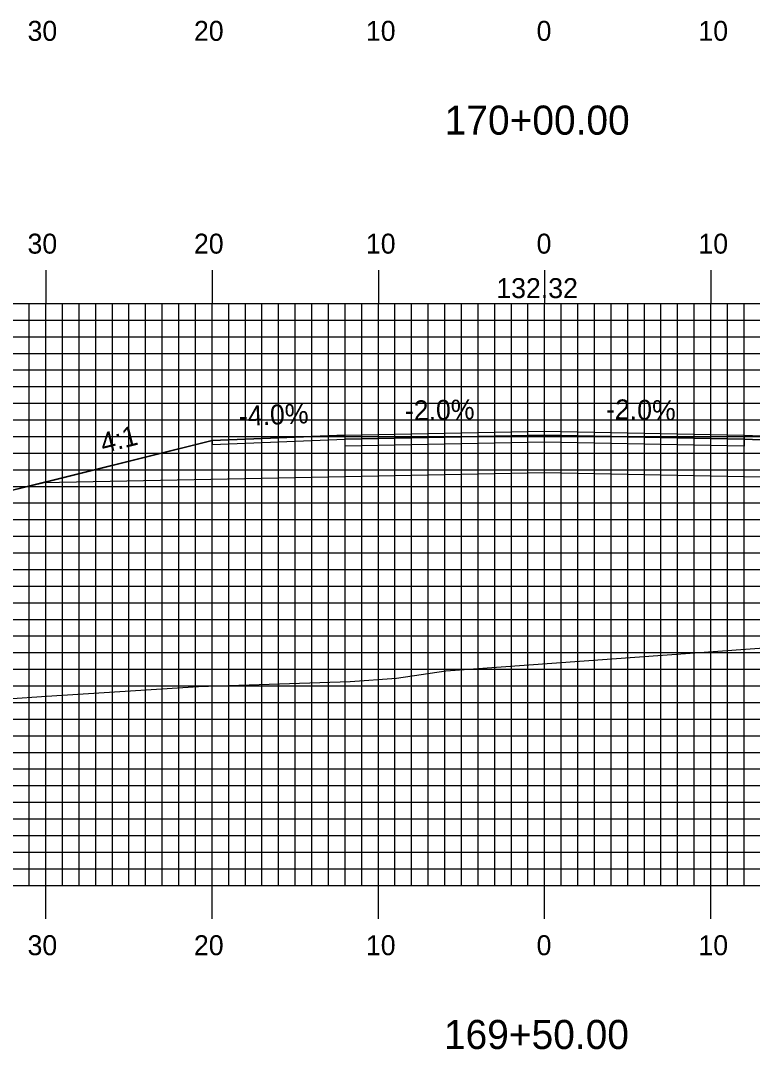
# Model space of a CAD drawing. Extents: x 1782254 to 1782597, y 442591 to 442811.
# Drawn here: x 1782387.9 to 1782431.9, y 442653.8 to 442715.7 of the extents above; entities that cross this region are included whole.
import ezdxf

# ---------------------------------------------------------------- set-up
doc = ezdxf.new("R2010")
doc.units = 0
for name, color, linetype in [('ANNOTATION', 7, 'Continuous'), ('D_Roadway_Centerline', 7, 'Continuous'), ('D_Roadway_Centerline_Text', 7, 'Continuous'), ('D_Roadway_Edge_Shoulder', 7, 'Continuous'), ('D_Roadway_Edge_TW', 7, 'Continuous'), ('D_Roadway_Pavement', 7, 'Continuous'), ('D_Roadway_SlopeLines', 7, 'Continuous'), ('D_Roadway_SubGrade', 7, 'Continuous'), ('H_V ANNOTATION', 7, 'Continuous'), ('MAJOR', 7, 'Continuous'), ('MINOR', 7, 'Continuous'), ('S_Roadway_Centerline', 7, 'Continuous')]:
    doc.layers.add(name, color=color, linetype=linetype)

msp = doc.modelspace()

# ---------------------------------------------------------------- linework, layer by layer
at = {"layer": 'D_Roadway_Centerline'}
msp.add_lwpolyline([(1782344.924, 442673.258), (1782387.434, 442687.428), (1782389.26, 442687.884), (1782399.434, 442690.428), (1782407.434, 442690.748), (1782419.434, 442690.988), (1782431.434, 442690.748), (1782439.434, 442690.428), (1782449.608, 442687.884), (1782468.362, 442683.196)], dxfattribs=at)
at = {"layer": 'D_Roadway_Edge_Shoulder'}
for points in [[(1782407.434, 442690.748), (1782399.434, 442690.428), (1782399.434, 442690.178), (1782407.434, 442690.498)], [(1782431.434, 442690.748), (1782439.434, 442690.428), (1782439.434, 442690.178), (1782431.434, 442690.498)]]:
    msp.add_lwpolyline(points, close=True, dxfattribs=at)
at = {"layer": 'D_Roadway_Edge_TW'}
msp.add_lwpolyline([(1782407.434, 442690.498), (1782407.434, 442690.748), (1782419.434, 442690.988), (1782431.434, 442690.748), (1782431.434, 442690.498), (1782419.434, 442690.738)], close=True, dxfattribs=at)
at = {"layer": 'D_Roadway_Pavement'}
msp.add_lwpolyline([(1782407.434, 442690.081), (1782407.434, 442690.498), (1782419.434, 442690.738), (1782431.434, 442690.498), (1782431.434, 442690.081), (1782419.434, 442690.321)], close=True, dxfattribs=at)
at = {"layer": 'D_Roadway_SlopeLines'}
msp.add_lwpolyline([(1782399.434, 442690.428), (1782387.434, 442687.428), (1782344.924, 442673.258)], dxfattribs=at)
at = {"layer": 'D_Roadway_SubGrade'}
msp.add_lwpolyline([(1782407.434, 442688.248), (1782389.26, 442687.884), (1782399.434, 442690.428), (1782399.434, 442690.178), (1782407.434, 442690.498), (1782419.434, 442690.738), (1782431.434, 442690.498), (1782439.434, 442690.178), (1782439.434, 442690.428), (1782449.608, 442687.884), (1782431.434, 442688.248), (1782419.434, 442688.488)], close=True, dxfattribs=at)
at = {"layer": 'MAJOR'}
for p, q in [((1782389.434, 442700.669), (1782389.434, 442698.665)), ((1782399.434, 442700.669), (1782399.434, 442698.665)), ((1782409.434, 442700.669), (1782409.434, 442698.665)), ((1782419.434, 442700.669), (1782419.434, 442698.665)), ((1782429.434, 442700.669), (1782429.434, 442698.665)), ((1782279.434, 442698.665), (1782559.434, 442698.665)), ((1782279.434, 442698.665), (1782559.434, 442698.665)), ((1782389.434, 442663.665), (1782389.434, 442698.665)), ((1782399.434, 442663.665), (1782399.434, 442698.665)), ((1782409.434, 442663.665), (1782409.434, 442698.665)), ((1782419.434, 442663.665), (1782419.434, 442698.665)), ((1782429.434, 442663.665), (1782429.434, 442698.665)), ((1782279.434, 442693.665), (1782559.434, 442693.665)), ((1782279.434, 442688.665), (1782559.434, 442688.665)), ((1782279.434, 442683.665), (1782559.434, 442683.665)), ((1782279.434, 442678.665), (1782559.434, 442678.665)), ((1782279.434, 442673.665), (1782559.434, 442673.665)), ((1782279.434, 442668.665), (1782559.434, 442668.665)), ((1782279.434, 442663.665), (1782559.434, 442663.665)), ((1782279.434, 442663.665), (1782559.434, 442663.665)), ((1782389.434, 442661.661), (1782389.434, 442663.665)), ((1782399.434, 442661.661), (1782399.434, 442663.665)), ((1782409.434, 442661.661), (1782409.434, 442663.665)), ((1782419.434, 442661.661), (1782419.434, 442663.665)), ((1782429.434, 442661.661), (1782429.434, 442663.665))]:
    msp.add_line(p, q, dxfattribs=at)
at = {"layer": 'MINOR'}
for p, q in [((1782388.434, 442663.665), (1782388.434, 442698.665)), ((1782390.434, 442663.665), (1782390.434, 442698.665)), ((1782391.434, 442663.665), (1782391.434, 442698.665)), ((1782392.434, 442663.665), (1782392.434, 442698.665)), ((1782393.434, 442663.665), (1782393.434, 442698.665)), ((1782394.434, 442663.665), (1782394.434, 442698.665)), ((1782395.434, 442663.665), (1782395.434, 442698.665)), ((1782396.434, 442663.665), (1782396.434, 442698.665)), ((1782397.434, 442663.665), (1782397.434, 442698.665)), ((1782398.434, 442663.665), (1782398.434, 442698.665)), ((1782400.434, 442663.665), (1782400.434, 442698.665)), ((1782401.434, 442663.665), (1782401.434, 442698.665)), ((1782402.434, 442663.665), (1782402.434, 442698.665)), ((1782403.434, 442663.665), (1782403.434, 442698.665)), ((1782404.434, 442663.665), (1782404.434, 442698.665)), ((1782405.434, 442663.665), (1782405.434, 442698.665)), ((1782406.434, 442663.665), (1782406.434, 442698.665)), ((1782407.434, 442663.665), (1782407.434, 442698.665)), ((1782408.434, 442663.665), (1782408.434, 442698.665)), ((1782410.434, 442663.665), (1782410.434, 442698.665)), ((1782411.434, 442663.665), (1782411.434, 442698.665)), ((1782412.434, 442663.665), (1782412.434, 442698.665)), ((1782413.434, 442663.665), (1782413.434, 442698.665)), ((1782414.434, 442663.665), (1782414.434, 442698.665)), ((1782415.434, 442663.665), (1782415.434, 442698.665)), ((1782416.434, 442663.665), (1782416.434, 442698.665)), ((1782417.434, 442663.665), (1782417.434, 442698.665)), ((1782418.434, 442663.665), (1782418.434, 442698.665)), ((1782420.434, 442663.665), (1782420.434, 442698.665)), ((1782421.434, 442663.665), (1782421.434, 442698.665)), ((1782422.434, 442663.665), (1782422.434, 442698.665)), ((1782423.434, 442663.665), (1782423.434, 442698.665)), ((1782424.434, 442663.665), (1782424.434, 442698.665)), ((1782425.434, 442663.665), (1782425.434, 442698.665)), ((1782426.434, 442663.665), (1782426.434, 442698.665)), ((1782427.434, 442663.665), (1782427.434, 442698.665)), ((1782428.434, 442663.665), (1782428.434, 442698.665)), ((1782430.434, 442663.665), (1782430.434, 442698.665)), ((1782431.434, 442663.665), (1782431.434, 442698.665)), ((1782279.434, 442697.665), (1782559.434, 442697.665)), ((1782279.434, 442696.665), (1782559.434, 442696.665)), ((1782279.434, 442695.665), (1782559.434, 442695.665)), ((1782279.434, 442694.665), (1782559.434, 442694.665)), ((1782279.434, 442692.665), (1782559.434, 442692.665)), ((1782279.434, 442691.665), (1782559.434, 442691.665)), ((1782279.434, 442690.665), (1782559.434, 442690.665)), ((1782279.434, 442689.665), (1782559.434, 442689.665)), ((1782279.434, 442687.665), (1782559.434, 442687.665)), ((1782279.434, 442686.665), (1782559.434, 442686.665)), ((1782279.434, 442685.665), (1782559.434, 442685.665)), ((1782279.434, 442684.665), (1782559.434, 442684.665)), ((1782279.434, 442682.665), (1782559.434, 442682.665)), ((1782279.434, 442681.665), (1782559.434, 442681.665)), ((1782279.434, 442680.665), (1782559.434, 442680.665)), ((1782279.434, 442679.665), (1782559.434, 442679.665)), ((1782279.434, 442677.665), (1782559.434, 442677.665)), ((1782279.434, 442676.665), (1782559.434, 442676.665)), ((1782279.434, 442675.665), (1782559.434, 442675.665)), ((1782279.434, 442674.665), (1782559.434, 442674.665)), ((1782279.434, 442672.665), (1782559.434, 442672.665)), ((1782279.434, 442671.665), (1782559.434, 442671.665)), ((1782279.434, 442670.665), (1782559.434, 442670.665)), ((1782279.434, 442669.665), (1782559.434, 442669.665)), ((1782279.434, 442667.665), (1782559.434, 442667.665)), ((1782279.434, 442666.665), (1782559.434, 442666.665)), ((1782279.434, 442665.665), (1782559.434, 442665.665)), ((1782279.434, 442664.665), (1782559.434, 442664.665))]:
    msp.add_line(p, q, dxfattribs=at)
at = {"layer": 'S_Roadway_Centerline'}
msp.add_lwpolyline([(1782331.816, 442672.41), (1782339.364, 442672.788), (1782341.359, 442672.923), (1782352.851, 442674.003), (1782362.865, 442674.079), (1782367.052, 442674.135), (1782384.649, 442674.78), (1782387.133, 442674.881), (1782389.481, 442675.054), (1782398.618, 442675.623), (1782407.746, 442675.93), (1782410.518, 442676.121), (1782413.501, 442676.564), (1782433.175, 442677.993), (1782437.452, 442678.655), (1782453.26, 442681.007), (1782460.569, 442682.018), (1782474.99, 442684.196)], dxfattribs=at)

# ---------------------------------------------------------------- texts
at = {"layer": 'ANNOTATION'}
for s, rotation, p in [('-2.0%', 1.14576, (1782411.04, 442691.62)), ('-2.0%', 358.85424, (1782423.12, 442691.714)), ('-4.0%', 2.29061, (1782401.066, 442691.295)), ('4:1', 14.03624, (1782392.883, 442689.651))]:
    msp.add_text(s, height=1.2, rotation=rotation, dxfattribs=at).set_placement(p)
at = {"layer": 'D_Roadway_Centerline'}
for s, p in [('C', (1782419.429, 442690.988)), ('L', (1782419.434, 442690.98))]:
    msp.add_text(s, height=0.0146, dxfattribs=at).set_placement(p)
at = {"layer": 'D_Roadway_Centerline_Text'}
msp.add_text('132.32', height=1.2, dxfattribs=at).set_placement((1782416.528, 442698.989))
at = {"layer": 'H_V ANNOTATION'}
for s, height, p in [('30', 1.2, (1782388.331, 442714.465)), ('20', 1.2, (1782398.342, 442714.465)), ('10', 1.2, (1782408.685, 442714.465)), ('0', 1.2, (1782418.952, 442714.465)), ('10', 1.2, (1782428.685, 442714.465)), ('170+00.00', 1.75, (1782413.425, 442708.821)), ('30', 1.2, (1782388.331, 442701.665)), ('20', 1.2, (1782398.342, 442701.665)), ('10', 1.2, (1782408.685, 442701.665)), ('0', 1.2, (1782418.952, 442701.665)), ('10', 1.2, (1782428.685, 442701.665)), ('30', 1.2, (1782388.331, 442659.465)), ('20', 1.2, (1782398.342, 442659.465)), ('10', 1.2, (1782408.685, 442659.465)), ('0', 1.2, (1782418.952, 442659.465)), ('10', 1.2, (1782428.685, 442659.465)), ('169+50.00', 1.75, (1782413.379, 442653.821))]:
    msp.add_text(s, height=height, dxfattribs=at).set_placement(p)

doc.saveas('drawing.dxf')
